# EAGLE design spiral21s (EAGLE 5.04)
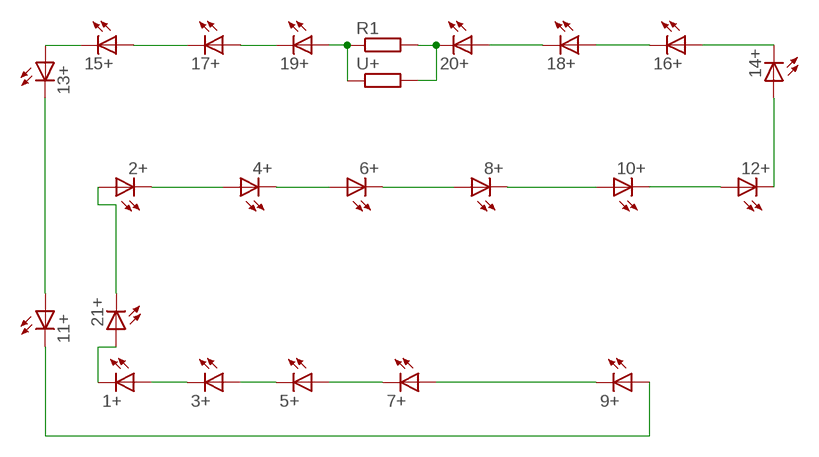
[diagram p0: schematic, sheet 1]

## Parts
1+  LEDCHIPLED_1206  [CHIPLED_1206]
2+  LEDCHIPLED_1206  [CHIPLED_1206]
3+  LEDCHIPLED_1206  [CHIPLED_1206]
4+  LEDCHIPLED_1206  [CHIPLED_1206]
5+  LEDCHIPLED_1206  [CHIPLED_1206]
6+  LEDCHIPLED_1206  [CHIPLED_1206]
7+  LED5MM  [LED5MM]
8+  LED5MM  [LED5MM]
9+  LED5MM  [LED5MM]
10+  LED5MM  [LED5MM]
11+  LED5MM  [LED5MM]
12+  LED5MM  [LED5MM]
13+  LED5MM  [LED5MM]
14+  LED5MM  [LED5MM]
15+  LED5MM  [LED5MM]
16+  LED5MM  [LED5MM]
17+  LED5MM  [LED5MM]
18+  LED5MM  [LED5MM]
19+  LED5MM  [LED5MM]
20+  LED5MM  [LED5MM]
21+  LEDCHIPLED_1206  [CHIPLED_1206]
R1  R-EU_R1206  [R1206]
U+  R-EU_0204/2V  [0204V]

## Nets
MINUS: 20+.K(C) R1.2 U+.2
N1-3: 1+.A 3+.C
N2-4: 2+.C 4+.A
N2-21: 2+.A 21+.C
N3-5: 3+.A 5+.C
N4-6: 4+.C 6+.A
N5-7: 5+.A 7+.K(C)
N6-8: 6+.C 8+.A
N7-9: 7+.A 9+.K(C)
N8-10: 8+.K(C) 10+.A
N9-11: 9+.A 11+.K(C)
N10-12: 10+.K(C) 12+.A
N11-13: 11+.A 13+.K(C)
N12-14: 12+.K(C) 14+.A
N13-15: 13+.A 15+.K(C)
N14-16: 14+.K(C) 16+.A
N15-17: 15+.A 17+.K(C)
N16-18: 16+.K(C) 18+.A
N17-19: 17+.A 19+.K(C)
N18-20: 18+.K(C) 20+.A
N21-1: 1+.C 21+.A
PLUS: 19+.A R1.1 U+.1

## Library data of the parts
1+ 2+ 3+ 4+ 5+ 6+ 7+ 8+ 9+ 10+ 11+ 12+ 13+ 14+ 15+ 16+ 17+ 18+ 19+ 20+ 21+ = led(2):LED: LED
R1 U+ = rcl-2:R-EU_: RESISTOR, European symbol

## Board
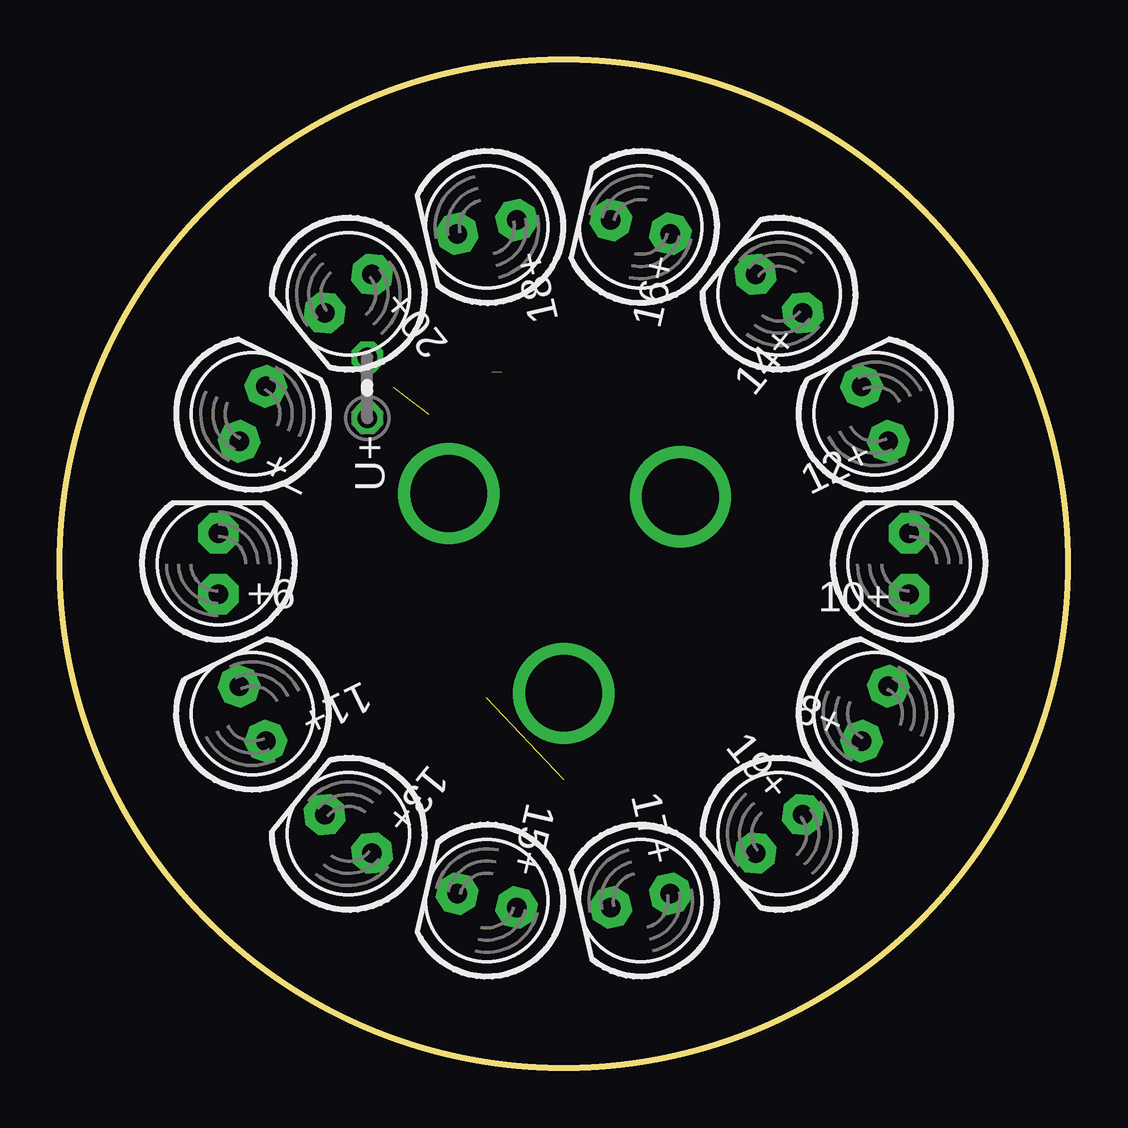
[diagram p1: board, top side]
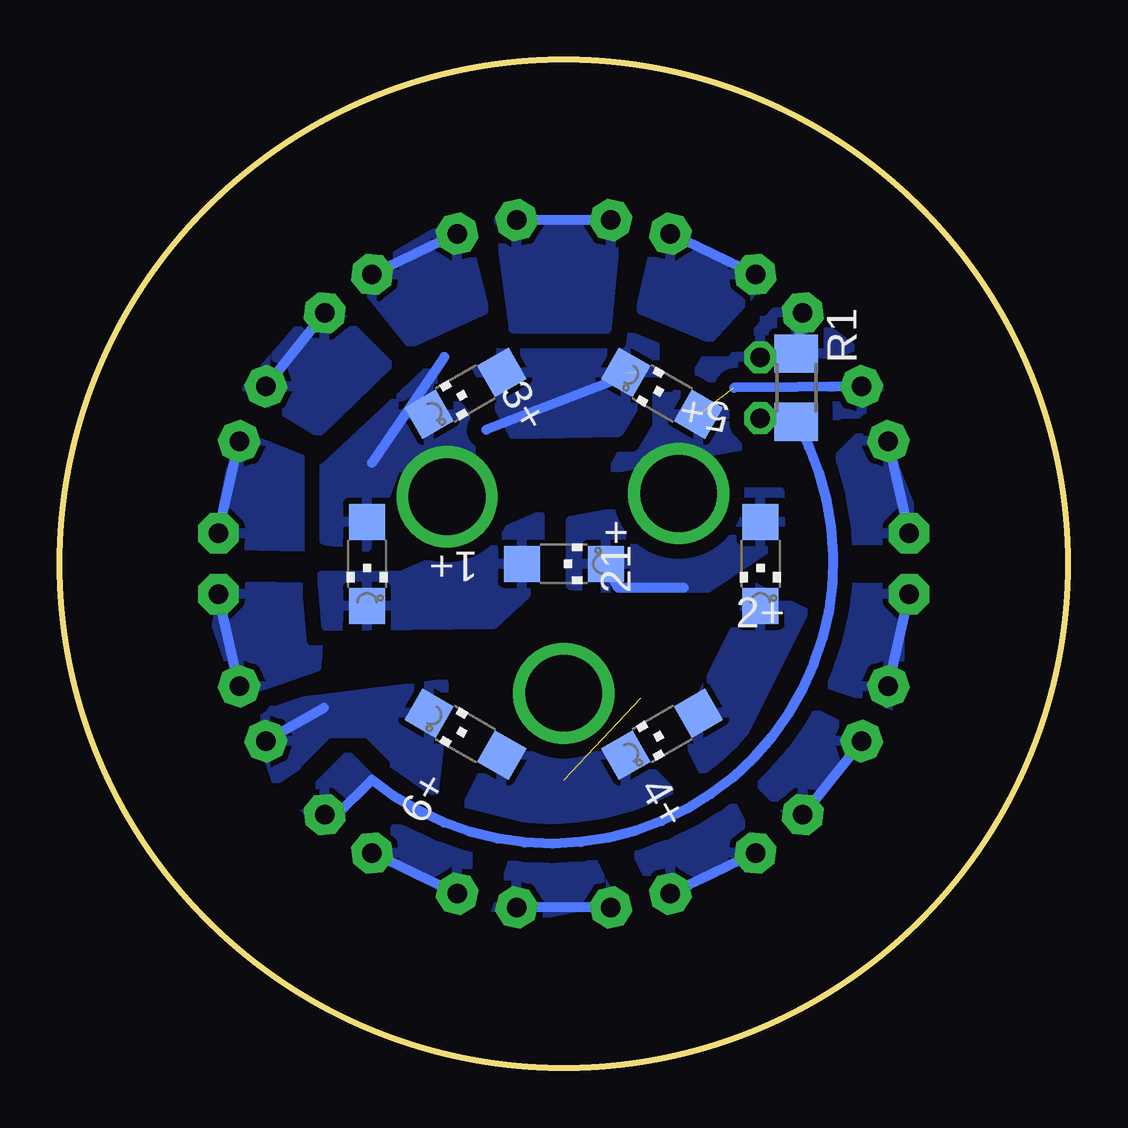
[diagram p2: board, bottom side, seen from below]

Size 42 x 42 mm. Coordinates in mm from the lower left corner, seen from the top.
Outline: circle at 21,21 radius 21
Copper layers (1*16): Top 0.035mm / dielectric 1.5mm / Bottom 0.035mm
Design rules "default": minimum track width 10mil, minimum drill 24mil, track to track 8mil, track to pad 8mil, pad to pad 8mil, via to via 8mil, smd to smd 8mil, copper to edge 40mil, drill to drill 8mil, minimum pad ring 10mil, minimum via ring 8mil, stop-mask expansion 4mil, vias tented up to drill 0mil, thermal gap 10mil

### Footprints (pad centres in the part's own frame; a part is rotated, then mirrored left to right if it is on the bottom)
CHIPLED_1206 = smd 1.5 x 1.5: A 0,-1.75; C 0,1.75
LED5MM = drill 0.813 pad 1.676 octagon: A -1.27,0; K 1.27,0
R1206 = smd 1.6 x 1.803: 1 -1.422,0; 2 1.422,0
0204V = drill 0.813 octagon: 1 -1.27,0; 2 1.27,0

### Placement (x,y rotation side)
1+  29.2,21 180 bottom
2+  12.8,21 180 bottom
3+  25.1,28.1 120 bottom
4+  16.9,13.9 120 bottom
5+  16.9,28.1 60 bottom
6+  25.1,13.9 60 bottom
7+  8.03,27.25 64 top
8+  33.97,14.75 64 top
9+  6.6,21 90 top
10+  35.4,21 90 top
11+  8.03,14.75 116 top
12+  33.97,27.25 116 top
13+  12.02,9.74 141 top
14+  29.98,32.26 141 top
15+  17.8,6.96 167 top
16+  24.2,35.04 167 top
17+  24.2,6.96 193 top
18+  17.8,35.04 193 top
19+  29.98,9.74 219 top
20+  12.02,32.26 219 top
21+  21,21 270 bottom
R1  11.31,28.34 90 bottom
U+  12.81,28.34 90 top

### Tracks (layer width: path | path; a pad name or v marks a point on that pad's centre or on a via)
HOL1  (via drill 3.2)
  other vias: 21,15.6
MINUS
  Bottom 0.406: U+.2 R1.2 20+.K
  pour Bottom (isolate 0.61, rank 3): 9,30 16,28 13,33
N1-3  (via drill 3.2)
  Bottom 0.406: 29,25.2 25.98,29.62
  other vias: 25.87,23.79
  pour Bottom (isolate 0.61): 24,26 26.7,29 31,25 31,22 29.2,21.7 28,25
N2-4
  pour Bottom (isolate 0.61, rank 2): 13,20 11,19 14,13 15,12 16,14
N2-21
  Bottom 0.406: 21+.C 18.73,20 16,20
  pour Bottom (isolate 0.61, rank 2): 12,24 12,22 15,20 20,20 20.7,20.1 20.7,22.8 14.2,24
N3-5  (1 unrouted)
  Bottom 0.406: 18,29 24.23,26.59
  pour Bottom (isolate 0.61, rank 3): 17.2,29 17.2,30.7 25.2,30.2 23.1,26.4 18.7,26.5
N4-6  (1 unrouted)
  pour Bottom (isolate 0.61, rank 2): 18,13 17,12 16,11 21,10 25,11 24,13 20,13
N5-7  (via drill 3.2)  (1 unrouted)
  Bottom 0.406: 7+.K 13.9,28.34
  other vias: 16.21,23.93
  pour Bottom (isolate 0.61, rank 4): 8,29 16.8,28.9 18.9,25 10.9,26.4 7.6,26.8
N6-8
  Bottom 0.406: 31,15 8+.A
  pour Bottom (isolate 0.61, rank 3): 26,15 26,16 34,15 33,12 30,14 26.4,11.5
N7-9
  Bottom 0.406: 9+.K 7+.A
  pour Bottom (isolate 0.61, rank 2): 8,27 10,25 9,22 6,22
N8-10
  Bottom 0.406: 8+.K 10+.A
  pour Bottom (isolate 0.61, rank 2): 31,20 36.1,20.1 34.5,15.6 31.3,16.7
N9-11
  Bottom 0.406: 11+.K 9+.A
  pour Bottom (isolate 0.61, rank 2): 7,20 9,20 10,16 7,15
N10-12
  Bottom 0.406: 10+.K 12+.A
  pour Bottom (isolate 0.61, rank 2): 31,25 34.6,26.4 35.5,21.8 31.1,21.7
N11-13
  Bottom 0.406: 11+.A 13+.K
  pour Bottom (isolate 0.61, rank 2): 9,14 11,15 13,12 11,10
N12-14
  Bottom 0.406: 14+.A 12+.K
  pour Bottom (isolate 0.61, rank 2): 31,32 34.2,28.3 31.2,26.5 28.3,29.3
N13-15
  Bottom 0.406: 13+.A 15+.K
  pour Bottom (isolate 0.61, rank 2): 13,9 14,11 18,9 17,7
N14-16
  Bottom 0.406: 16+.A 14+.K
  pour Bottom (isolate 0.61, rank 2): 26,35 29.6,32.9 27.4,30.2 24.3,31.6 25.2,35.2
N15-17
  Bottom 0.406: 15+.A 17+.K
  pour Bottom (isolate 0.61, rank 2): 19,7 20,9 23,9 24,6
N16-18
  Bottom 0.406: 18+.A 16+.K
  pour Bottom (isolate 0.61, rank 2): 19,35 23.7,35.3 23.1,30.8 19.2,30.8 18.8,35
N17-19
  Bottom 0.406: 17+.A 19+.K
  pour Bottom (isolate 0.61, rank 2): 25,7 25,9 28,10 29,9
N18-20
  Bottom 0.406: 20+.A 18+.K
  pour Bottom (isolate 0.61, rank 2): 13,33 17.1,34.7 17.8,31.6 14.9,30.4 12.9,32.6
N21-1
  pour Bottom (isolate 0.61): 22,22 22,23 27.8,20.5 31.1,20.5 30.9,18.4 23.9,18.5 22.6,19.7
PLUS
  Bottom 0.406: 19+.A 30.46,10.54 29,12 arc-159 R1.1 U+.1
  pour Bottom (isolate 0.61, rank 2): 29,12 30,13 32,11 31,10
